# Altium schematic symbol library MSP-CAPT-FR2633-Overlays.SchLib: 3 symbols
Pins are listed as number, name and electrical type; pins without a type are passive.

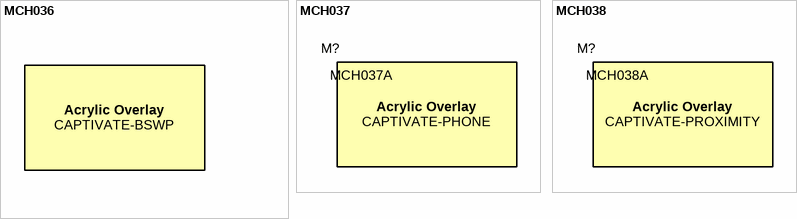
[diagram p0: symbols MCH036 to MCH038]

## MCH036
designator M?, comment MCH036A
CAPTIVATE-BSWP Overlay; SymbolCreator: a0273983; CompType: Overlay Plastic; U/M: EA, IN, or GM
footprint MCH036 (CAPTIVATE-BSWP Overlay)

## MCH037
designator M?, comment MCH037A
CAPTIVATE-PHONE Overlay; SymbolCreator: a0273983; CompType: Overlay Plastic; U/M: EA, IN, or GM
footprint MCH037 (CAPTIVATE-PHONE Overlay)

## MCH038
designator M?, comment MCH038A
CAPTIVATE-PROXIMITY Overlay; SymbolCreator: a0273983; CompType: Overlay Plastic; U/M: EA, IN, or GM
footprint MCH038 (CAPTIVATE-BSWP Overlay)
